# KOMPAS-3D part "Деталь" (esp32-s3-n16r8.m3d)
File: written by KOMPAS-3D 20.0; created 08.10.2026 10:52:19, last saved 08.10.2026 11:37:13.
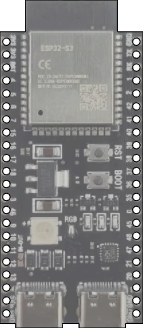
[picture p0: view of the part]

Document properties: Полное имя файла: D:\RicWork\Project-EPS32\box_compas\esp32-s3-n16r8.m3d

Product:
- Part/product: Деталь
    Масса: 0.019451

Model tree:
1. Эскиз:1
2. Элемент выдавливания:1
     Расстояние 1 = 1.5
3. Эскиз:2  (with: Элемент выдавливания:1)
4. Элемент выдавливания:3
     Расстояние 2 = 1.5
5. Эскиз:3  (with: Элемент выдавливания:1)
6. Элемент выдавливания:4
     Расстояние 2 = 1.5
7. Массив по сетке:1  (with: Элемент выдавливания:4, Эскиз:3)  (44 pattern instances)
     Шаг 1 = 25.4; Угол раствора = -90; Шаг 2 = 2.54

Referenced files in D:\RicWork\Project-EPS32\box_compas\: esp32-s3-n16r8.png
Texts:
  esp32-s3-n16r8.png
